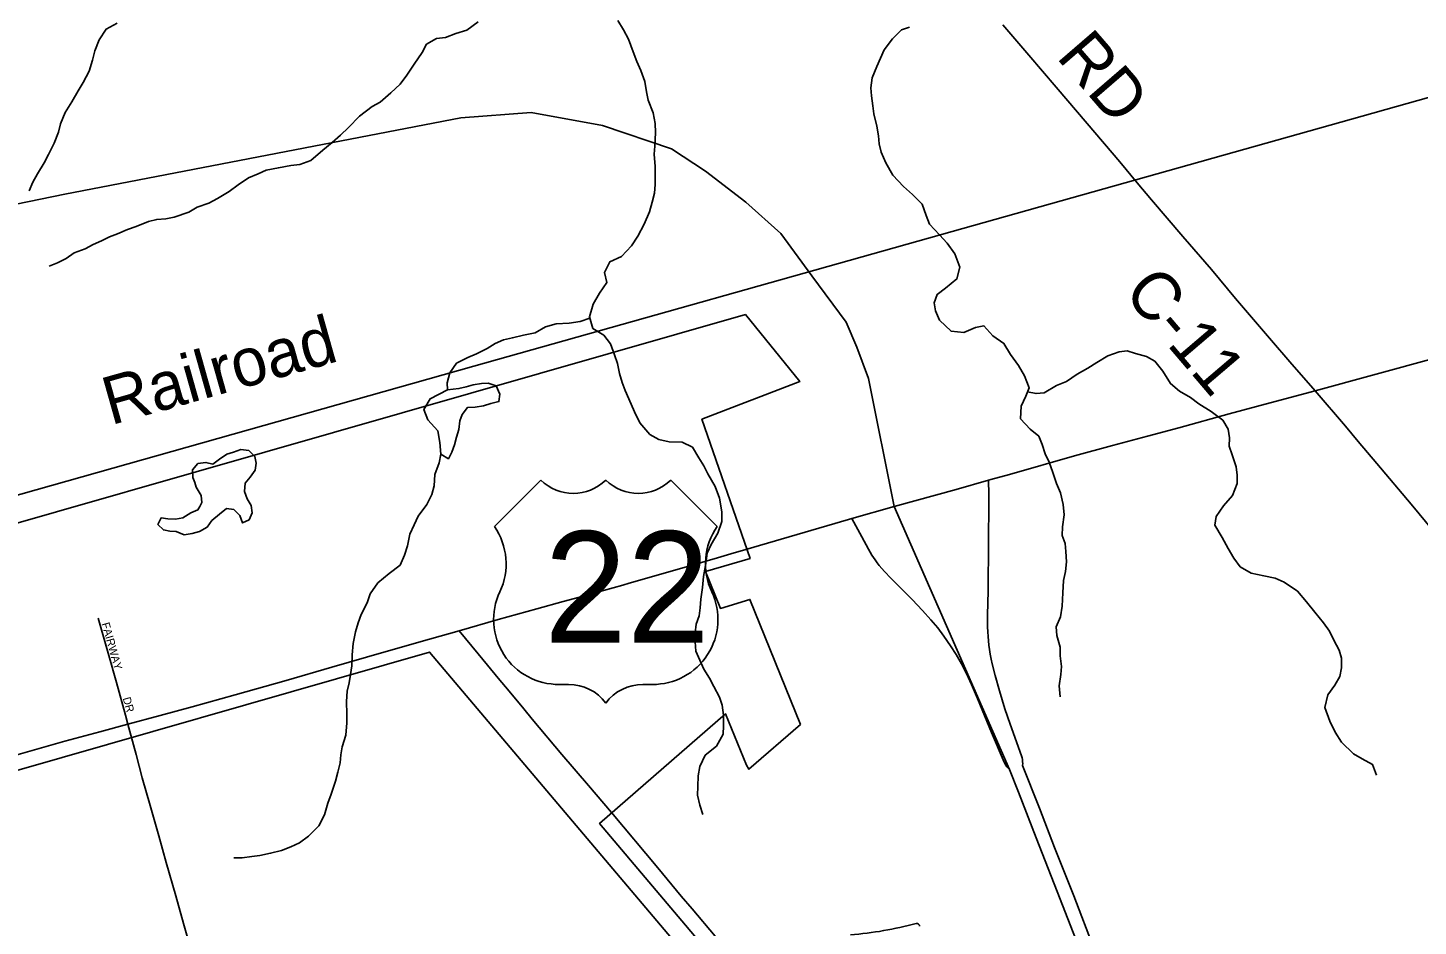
# Model space of a CAD drawing. Extents: x 1442749 to 1756758, y 235267 to 677782.
# Drawn here: x 1603104 to 1611789, y 530141 to 535753 of the extents above; entities that cross this region are included whole.
import ezdxf

# ---------------------------------------------------------------- set-up
doc = ezdxf.new("R2010")
doc.units = 0
for name, color, linetype in [('GM_P_State_Alignment', 7, 'Continuous'), ('GM_X_City_Street', 7, 'Continuous'), ('GM_X_City_Street_Text', 7, 'Continuous'), ('GM_X_Corporation', 7, 'Continuous'), ('GM_X_County_Road', 7, 'Continuous'), ('GM_X_County_Road_Text', 7, 'Continuous'), ('GM_X_Minor_Lake', 7, 'Continuous'), ('GM_X_Minor_River', 7, 'Continuous'), ('GM_X_Rail_Line', 7, 'Continuous'), ('GM_X_Rail_Line_Text', 7, 'Continuous'), ('GM_X_State_Route', 7, 'Continuous'), ('GM_X_State_Shield', 7, 'Continuous'), ('GM_X_US_Location', 7, 'Continuous'), ('GM_X_US_Route', 7, 'Continuous'), ('GM_X_US_Shield', 7, 'Continuous')]:
    doc.layers.add(name, color=color, linetype=linetype)

msp = doc.modelspace()

# ---------------------------------------------------------------- linework, layer by layer
at = {"layer": 'GM_P_State_Alignment'}
for points in [[(1602490.9, 534540.5), (1603334.8, 534713.2), (1605809.5, 535190.7), (1606248.1, 535223.2), (1606694.8, 535141.9), (1607125.2, 534995.7), (1607336.4, 534857.7), (1607588.2, 534662.8), (1607807.4, 534467.9), (1608002.5, 534203.6), (1608216, 533914.5), (1608283.2, 533757.6), (1608356.1, 533561.4), (1608516.5, 532762.3)], [(1608516.5, 532762.3), (1609236.7, 531120.1)]]:
    msp.add_lwpolyline(points, dxfattribs=at)
at = {"layer": 'GM_X_City_Street'}
for points in [[(1603728.9, 531403.4), (1603714, 531459.3), (1603656.9, 531664.2), (1603605.4, 531846.3), (1603543.5, 532064.9)], [(1604275.1, 529462.3), (1604235.3, 529602.6), (1604187.1, 529772.8), (1604133.1, 529961.9), (1604077.4, 530157.4), (1604028.1, 530330.8), (1603968.8, 530538.9), (1603921.7, 530706.1), (1603867.8, 530895.2), (1603819.1, 531068.8), (1603779.9, 531213.5), (1603741.1, 531356.6), (1603728.9, 531403.4)]]:
    msp.add_lwpolyline(points, dxfattribs=at)
at = {"layer": 'GM_X_Corporation'}
msp.add_lwpolyline([(1599850.2, 531747), (1607586.2, 533961), (1607925.7, 533543.2), (1607315, 533307.6), (1607615.7, 532438.7), (1607336.7, 532357), (1607430.1, 532125.8), (1607614.7, 532182.2), (1607930.3, 531401), (1607608.8, 531121.5), (1607592.4, 531146.6), (1607462.8, 531467.5), (1606675.9, 530783.4), (1609576.5, 527353.3), (1609668.7, 527239), (1609063.1, 526743.1), (1607767.9, 528274.8), (1607062.1, 527703.1), (1606189.4, 528248.5), (1606847.5, 528884.2), (1607206.9, 528613.3), (1607904.2, 529145.1), (1605613.8, 531853.4), (1602735.9, 531028)], dxfattribs=at)
at = {"layer": 'GM_X_County_Road'}
for points in [[(1611146.3, 533485.5), (1610988.1, 533665.5), (1610872.6, 533799.9), (1610648.7, 534061.7), (1610497.2, 534242.9), (1610319, 534448.8), (1610123.4, 534678.6), (1610034.7, 534784.1), (1609925, 534914.7), (1609721.3, 535155), (1609527.8, 535382.3), (1609356.5, 535581.3), (1609193.9, 535770.2)], [(1616061.8, 527721.7), (1615880.4, 527923.8), (1615777.9, 528043.3), (1615653.6, 528187.4), (1615413.7, 528469.9), (1615095.4, 528840.9), (1614595.4, 529430.5), (1614444.9, 529605.4), (1614212.9, 529877.4), (1614058.2, 530055.9), (1613941.2, 530193.2), (1613700.5, 530475.2), (1613366.2, 530866.9), (1613180.6, 531083.8), (1612938.5, 531368.8), (1612521.9, 531858.6), (1612333.3, 532081.4), (1612188.8, 532251.4), (1611885.9, 532609.5), (1611744.6, 532777.9), (1611530.6, 533030.9), (1611414.2, 533168.7), (1611334.2, 533264.3), (1611146.3, 533485.5)]]:
    msp.add_lwpolyline(points, dxfattribs=at)
at = {"layer": 'GM_X_Minor_Lake'}
for points in [[(1605725.1, 533491.2), (1605617.8, 533435.3), (1605576.9, 533367.6), (1605602.2, 533303.1), (1605665.5, 533234.2), (1605676.7, 533161.9), (1605683.9, 533089.6)], [(1605683.9, 533089.6), (1605731.6, 533060.9), (1605752.2, 533102.8), (1605768.7, 533146.8), (1605781.3, 533194.8), (1605795.9, 533242.7), (1605802.6, 533296.8), (1605817.1, 533336.8), (1605849.7, 533380.5), (1605897.8, 533382), (1605950, 533391.4), (1605996.3, 533404.9), (1606046.5, 533418.4), (1606053.1, 533464.4), (1606029.7, 533516.8), (1605979.7, 533533.5), (1605937.6, 533529.9), (1605885.4, 533522.5), (1605841.2, 533509), (1605797, 533499.4), (1605725.1, 533491.2)], [(1604456.5, 532856.9), (1604461.1, 532909), (1604493.7, 532946.7), (1604524.2, 532988.5), (1604530.8, 533032.6), (1604521.2, 533074.8), (1604483.6, 533113.3), (1604433.6, 533117.9), (1604389.3, 533102.4), (1604347, 533088.8), (1604300.6, 533057.3), (1604260.1, 533027.6), (1604216.1, 533038.2), (1604166, 533030.7), (1604133.4, 532991), (1604134.9, 532942.8), (1604146.5, 532912.6), (1604156.2, 532882.4), (1604185.7, 532831.9), (1604191.1, 532787.7), (1604177.7, 532762.7)], [(1604177.7, 532762.7), (1604166.5, 532741.9), (1604122.2, 532722.3), (1604071.8, 532692.8), (1604025.6, 532683.3), (1603977.5, 532685.9), (1603937.5, 532692.3), (1603916.9, 532650.5), (1603950.6, 532616), (1603990.6, 532609.5), (1604030.7, 532607), (1604080.5, 532586.4), (1604130.7, 532593.9), (1604177, 532607.4), (1604223.4, 532632.9), (1604253.9, 532674.7), (1604300.5, 532714.3), (1604345, 532749.9), (1604391, 532743.3), (1604428.7, 532706.8), (1604444.2, 532660.5), (1604486.5, 532680), (1604505, 532724), (1604499.6, 532768.2), (1604474, 532810.6), (1604456.5, 532856.9)]]:
    msp.add_lwpolyline(points, dxfattribs=at)
at = {"layer": 'GM_X_Minor_River'}
for points in [[(1603661.5, 535782.3), (1603592.9, 535745), (1603550, 535677.3), (1603523.1, 535609.4), (1603508.4, 535551.4), (1603487.5, 535481.5), (1603450.6, 535411.7), (1603418, 535359.9), (1603379, 535290.2), (1603338.2, 535224.4), (1603307.3, 535152.6), (1603294.6, 535100.6), (1603267.8, 535032.7), (1603232.8, 534960.9), (1603206.2, 534909.1), (1603165.3, 534841.3), (1603134.6, 534787.5), (1603111.9, 534733.6)], [(1605916.4, 535790.6), (1605845.6, 535737.3), (1605777.2, 535716), (1605712.8, 535692.7), (1605656.6, 535685.3), (1605594, 535649.9), (1605567.3, 535598), (1605516.4, 535526.4), (1605471.5, 535456.8), (1605430.7, 535401), (1605371.9, 535345.6), (1605305.1, 535288.2), (1605254.7, 535260.7), (1605175.8, 535201.4), (1605106.8, 535130), (1605056.1, 535082.4), (1605005.5, 535036.9), (1604946.8, 534987.4), (1604871.9, 534924.1), (1604803.4, 534898.8), (1604747.2, 534893.4), (1604668.9, 534878.3), (1604592.6, 534863.1), (1604542.2, 534839.6), (1604481.8, 534816.2), (1604417.1, 534770.8), (1604362.5, 534729.3), (1604287.8, 534686.1), (1604235.3, 534656.6), (1604160.9, 534631.4), (1604110.4, 534601.9), (1604017.9, 534568.8), (1603965.6, 534559.4), (1603909.5, 534556), (1603857.2, 534542.6), (1603780.7, 534511.4), (1603726.3, 534491.9), (1603663.9, 534466.6), (1603613.6, 534447.1), (1603563.1, 534421.6), (1603512.8, 534398.1), (1603462.4, 534372.6), (1603393.9, 534347.3), (1603343.4, 534311.8), (1603288.9, 534284.3), (1603236.6, 534262.9)], [(1606790.3, 535798.6), (1606825.7, 535740.1), (1606857, 535681.5), (1606886.2, 535603), (1606907.5, 535542.6), (1606932.9, 535486.1), (1606958.1, 535417.7), (1606969.4, 535353.3), (1606978.8, 535301.1), (1607009.9, 535220.5), (1607023.2, 535154.2), (1607024.5, 535098), (1607021.5, 535013.8), (1607016.9, 534963.7), (1607022, 534885.4), (1607023.3, 534827.2), (1607022.6, 534773.1), (1607018, 534719), (1607003.3, 534663), (1606986.5, 534603), (1606953.5, 534525.2), (1606914.6, 534451.4), (1606875.8, 534391.7), (1606812.9, 534324.2), (1606740.3, 534290.9), (1606705.5, 534225.2), (1606720.7, 534160.8), (1606675.9, 534095.1), (1606635, 534025.4), (1606612, 533947.4), (1606633.2, 533875), (1606702.8, 533832.1), (1606744.3, 533779.4), (1606769.5, 533710.9), (1606786.9, 533656.6), (1606800.2, 533594.3), (1606817.6, 533537.9), (1606835, 533487.6), (1606858.4, 533435.1), (1606893.6, 533354.5), (1606926.8, 533285.9), (1606990.1, 533213), (1607045.8, 533180.3), (1607109.8, 533167.5), (1607191.9, 533164.6), (1607255.7, 533133.8), (1607295, 533067.1), (1607326.5, 533016.6), (1607351.9, 532966.2), (1607397.1, 532887.4), (1607424.3, 532814.9), (1607439.3, 532728.5), (1607438.6, 532668.3), (1607413.7, 532596.4), (1607372.8, 532524.7), (1607348.1, 532470.8), (1607337.1, 532394.7), (1607324.3, 532324.6), (1607317.5, 532256.5), (1607308.6, 532184.4), (1607303.9, 532130.3), (1607297.3, 532080.2), (1607278.7, 532028.3), (1607272, 531974.2), (1607273.4, 531918), (1607276.7, 531859.8), (1607302.1, 531803.4), (1607327.5, 531746.9), (1607362.9, 531690.3), (1607388.3, 531637.9), (1607425.6, 531571.3), (1607441, 531520.9), (1607450.3, 531458.7), (1607449.5, 531392.5), (1607446.9, 531340.4), (1607406, 531266.6), (1607335.1, 531209.2), (1607302.2, 531139.4), (1607291.5, 531079.4), (1607288.7, 531013.2), (1607288.1, 530959), (1607301.4, 530896.7), (1607320.7, 530838.3)], [(1608611.7, 535755.7), (1608561.4, 535740.2), (1608504.6, 535682.7), (1608453.7, 535615.1), (1608408.3, 535511.3), (1608379.4, 535439.5), (1608370.7, 535377.4), (1608374.1, 535327.2), (1608383.3, 535264.9), (1608388.8, 535214.7), (1608407.9, 535138.3), (1608417.2, 535078), (1608422.6, 535027.8), (1608434, 534975.5), (1608463.3, 534909), (1608508.5, 534832.3), (1608573.8, 534761.3), (1608631.3, 534710.5), (1608690.7, 534651.7), (1608716, 534581.2), (1608737.4, 534526.8), (1608798.7, 534459.9), (1608846.2, 534407.2), (1608895.5, 534340.5), (1608926.6, 534257.9), (1608907.7, 534183.9), (1608836.8, 534126.5), (1608784.2, 534087), (1608765.6, 534035.1), (1608773, 533984.8), (1608798.4, 533926.4), (1608871.7, 533857.4), (1608951.8, 533848.4), (1609024.3, 533879.7), (1609076.5, 533891.1), (1609131.9, 533828.3), (1609201.5, 533781.4), (1609242.8, 533712.7), (1609292.1, 533643.9), (1609329.4, 533579.3), (1609358.6, 533504.8), (1609337.9, 533450.9), (1609309.1, 533389), (1609304.2, 533310.9), (1609365.5, 533246), (1609419.1, 533201.2), (1609440.5, 533150.8), (1609459.9, 533092.4), (1609483.3, 533040), (1609506.6, 532975.6), (1609529.9, 532907.1), (1609555.2, 532848.7), (1609572.4, 532774.2), (1609577.6, 532710), (1609566.7, 532635.9), (1609566.1, 532581.8), (1609583.5, 532531.4), (1609588.9, 532481.2), (1609592.2, 532417), (1609585.5, 532356.9), (1609572.8, 532300.9), (1609569.8, 532222.7), (1609564.9, 532140.5), (1609554.1, 532074.4), (1609527.2, 532010.6), (1609532.6, 531956.3), (1609551.8, 531883.9), (1609553.2, 531829.7), (1609560.4, 531763.5), (1609557.8, 531713.3), (1609546.9, 531643.3), (1609552.1, 531573)], [(1606614.7, 533938.2), (1606553.5, 533918), (1606485.2, 533906.8), (1606405, 533903.7), (1606338.7, 533884.4), (1606274.1, 533847), (1606199.7, 533831.8), (1606131.4, 533816.5), (1606075.1, 533803.1), (1606022.8, 533781.7), (1605972.3, 533750.2), (1605905.8, 533716.8), (1605853.4, 533693.4), (1605782.8, 533658.1), (1605740, 533598.4), (1605723.2, 533534.4), (1605725.1, 533491.2), (1605617.8, 533435.3), (1605576.9, 533367.6), (1605602.2, 533303.1), (1605665.5, 533234.2), (1605676.7, 533161.9), (1605683.9, 533089.6), (1605673.2, 533035.5), (1605646.3, 532961.6), (1605641.4, 532891.5), (1605626.8, 532837.5), (1605596, 532775.7), (1605543, 532702.1), (1605516.3, 532648.2), (1605489.5, 532590.3), (1605476.6, 532516.3), (1605457.9, 532458.3), (1605429.1, 532396.5), (1605360.4, 532343.1), (1605289.5, 532285.7), (1605242.6, 532216.1), (1605223.9, 532160.1), (1605187, 532088.3), (1605168.3, 532036.4), (1605151.6, 531980.4), (1605136.7, 531906.4), (1605129.9, 531836.2), (1605127.1, 531768.1), (1605120.4, 531714), (1605111.8, 531661.9), (1605099.1, 531609.9), (1605094.3, 531543.8), (1605097.4, 531465.5), (1605096.8, 531411.4), (1605089.9, 531335.2), (1605067, 531261.3), (1605058.4, 531211.2), (1605055.8, 531161.1), (1605041, 531103.1), (1605026.4, 531047.1), (1604999.3, 530965.2), (1604978.6, 530909.3), (1604957.7, 530837.3), (1604920.8, 530767.5), (1604857.9, 530704), (1604801.3, 530662.5), (1604746.9, 530637.1), (1604688.5, 530613.7), (1604620.2, 530596.4), (1604553.9, 530583.1), (1604503.7, 530575.7), (1604443.5, 530568.3), (1604391.4, 530568.9)], [(1609348.9, 533479.6), (1609402.2, 533468.2), (1609452.4, 533473.6), (1609529.1, 533518.9), (1609591.5, 533544.2), (1609658.2, 533589.6), (1609724.8, 533627), (1609781.3, 533662.4), (1609850, 533703.8), (1609920.4, 533729), (1609970.6, 533734.5), (1610022.5, 533717.8), (1610092.4, 533699), (1610144.2, 533670.3), (1610193.6, 533607.5), (1610242.7, 533530.8), (1610298.3, 533482), (1610366, 533443.1), (1610419.6, 533404.4), (1610495.2, 533355.4), (1610568.7, 533302.4), (1610602.1, 533245.8), (1610611.5, 533191.6), (1610608.9, 533139.5), (1610626.3, 533085.1), (1610651.5, 533010.6), (1610658.9, 532958.4), (1610658.2, 532906.2), (1610629.3, 532830.3), (1610572.4, 532766.8), (1610527.5, 532701.1), (1610518.9, 532645.1), (1610564, 532568.3), (1610601.3, 532499.7), (1610636.7, 532439.1), (1610678.1, 532386.5), (1610745.8, 532345.6), (1610825.8, 532328.7), (1610895.8, 532315.8), (1610951.6, 532289.1), (1611035.1, 532234), (1611092.4, 532167.1), (1611143.8, 532102.4), (1611197.1, 532035.6), (1611234.5, 531983), (1611262, 531928.5), (1611295.3, 531865.9), (1611310.7, 531815.6), (1611310, 531755.5), (1611299.4, 531701.4), (1611268.6, 531645.6), (1611225.8, 531585.9), (1611206.9, 531507.9), (1611237.9, 531421.3), (1611271.2, 531352.7), (1611310.5, 531290.1), (1611385.8, 531217), (1611439.6, 531186.3), (1611503.3, 531151.5), (1611528.6, 531085)]]:
    msp.add_lwpolyline(points, dxfattribs=at)
at = {"layer": 'GM_X_Rail_Line'}
msp.add_lwpolyline([(1602593, 532708.2), (1605889.2, 533638.1), (1608878.6, 534479.8), (1615229.4, 536269.1), (1618947.6, 537317.7), (1620089.8, 537639.4), (1622992.7, 538441.5), (1624973.8, 539013.5)], dxfattribs=at)
at = {"layer": 'GM_X_State_Route'}
for points in [[(1609105.6, 532927.3), (1609106.6, 532838.3), (1609107.1, 532783.6), (1609104.3, 532541.1), (1609102, 532233), (1609099.4, 532085.5), (1609099.3, 532010.1), (1609100.5, 531979.9), (1609102, 531951.1), (1609104.4, 531923.7), (1609107.7, 531895.7), (1609111.5, 531869.4), (1609116.3, 531840.7), (1609122.2, 531809.8), (1609128.9, 531779.6), (1609147, 531706.4), (1609173.4, 531611.7), (1609207.8, 531498.8), (1609240.2, 531403.8), (1609310.9, 531206.1), (1609314.8, 531193.4), (1609317, 531181.4), (1609318.3, 531168.3), (1609319, 531157.6), (1609318.1, 531145), (1609423.6, 530878.6), (1609517.8, 530633.6), (1609637.2, 530331.5), (1609766.1, 529997.9)], [(1608251, 532688.3), (1608314.3, 532573.5), (1608355.9, 532495.6), (1608376.9, 532458.6), (1608396.7, 532428.5), (1608409.5, 532411.2), (1608422.6, 532394.6), (1608454.8, 532357.5), (1608495.7, 532314.9), (1608627.5, 532182.6), (1608693.2, 532113.8), (1608745.7, 532055.3), (1608787.6, 532004.8), (1608827, 531952.4), (1608867.9, 531893), (1608902.9, 531837.6), (1608935.5, 531780.7), (1608967.3, 531719.6), (1608999.2, 531651.3), (1609035.6, 531562.8), (1609124.2, 531351.1), (1609196.6, 531181), (1609207.8, 531158.2), (1609213.4, 531147.5), (1609220.4, 531137.1), (1609227.5, 531128.4), (1609236.7, 531120.1)], [(1605798, 531986), (1605916.8, 531842), (1606053.1, 531678.9), (1606101, 531620.9)], [(1606101, 531620.9), (1606201.6, 531499)], [(1606201.6, 531499), (1606254.8, 531434.6), (1606438.9, 531213.1), (1606606.6, 531020), (1606749.3, 530850.7)], [(1609236.7, 531120.1), (1609291.7, 530978.1), (1609401.9, 530693.5), (1609533.9, 530357.5), (1609818.9, 529626.7), (1609915.2, 529382.4), (1610040.6, 529061.4), (1610089.8, 528929), (1610128.8, 528817.3), (1610153.9, 528739.1), (1610180.2, 528647.5), (1610211.3, 528530), (1610239.3, 528415), (1610258, 528324.9), (1610267.1, 528275.1), (1610276.5, 528221.4), (1610290.2, 528133.7), (1610300.6, 528052.2), (1610310.7, 527954.2), (1610325.6, 527780.8), (1610331.5, 527700.6)], [(1606749.3, 530850.7), (1607038.6, 530505.9), (1607185.7, 530329.4), (1607252.9, 530248.7), (1607396.9, 530078.3), (1607485.3, 529972.6), (1607684.4, 529737), (1608040.6, 529308), (1608138.9, 529192.7), (1608265.8, 529043.6), (1608364.3, 528926.4), (1608680.7, 528550.5), (1608776.4, 528436.8), (1609018.1, 528147), (1609085.4, 528067.3), (1609143.7, 527999.6), (1609281.8, 527832.8), (1609404.3, 527687.1), (1609595.4, 527457.6), (1609730.5, 527290.9)]]:
    msp.add_lwpolyline(points, dxfattribs=at)
at = {"layer": 'GM_X_State_Shield'}
for centre, major_axis, start_param, end_param in [((1608054.3, 531555.5), (1845.5, 0), 4.814394, 5.042369), ((1608654.9, 530143.4), (19.4, 0), 6.141152, 7.989035)]:
    msp.add_ellipse(centre, major_axis=major_axis, ratio=0.8, start_param=start_param, end_param=end_param, dxfattribs=at)
at = {"layer": 'GM_X_US_Route'}
for points in [[(1611114.3, 533477), (1611146.3, 533485.5), (1611884.1, 533686), (1612184.8, 533768.1), (1612773.7, 533928), (1612922.6, 533968.1), (1613097, 534014.1), (1613213, 534045.8), (1613334.4, 534079), (1613521.5, 534128.3), (1613977.5, 534251.7), (1614297.1, 534339.2), (1614683.6, 534443), (1615227.3, 534594.2), (1615651.8, 534708.6), (1615838.5, 534759.6), (1616075, 534827.4), (1616654.2, 534997.3), (1617126.4, 535135.7), (1617371.7, 535208.7), (1617599.3, 535275.1)], [(1608251, 532688.3), (1608516.5, 532762.3), (1608902.7, 532869.6), (1609105.6, 532927.3), (1609120.1, 532931.3), (1609236.3, 532963.4), (1609642.3, 533079.1), (1609880.5, 533143.3), (1610098, 533201), (1610294.7, 533254.1), (1610607.7, 533340.6), (1610778.6, 533387.2), (1611114.3, 533477)], [(1607674, 532518.8), (1607909.8, 532588.1), (1608230.8, 532682.4)], [(1608230.8, 532682.4), (1608251, 532688.3)], [(1607567.7, 532487.6), (1607674, 532518.8)], [(1606859.4, 532283.2), (1607072.8, 532343.2), (1607268.7, 532399.5), (1607412, 532441.4), (1607517.1, 532472.7), (1607567.7, 532487.6)], [(1606448, 532168.2), (1606519.8, 532187.6), (1606820.4, 532272.2), (1606859.4, 532283.2)], [(1605798, 531986), (1606042, 532056.3), (1606282.8, 532123.4), (1606448, 532168.2)], [(1603366, 531304.5), (1603552.7, 531355.8), (1603728.9, 531403.4), (1603931.6, 531458.1), (1604131.2, 531511), (1604398.2, 531585.7), (1604716.9, 531676), (1605003.7, 531758.7), (1605328.4, 531852.1), (1605612.7, 531933.9), (1605798, 531986)], [(1599333.3, 530149.7), (1599393.1, 530166.5), (1599694.5, 530253.4), (1599900.6, 530311.5), (1600124.2, 530374.6), (1600399.9, 530455.2), (1600769, 530566), (1601060.8, 530650.9), (1601380.7, 530741.9), (1601496.5, 530774.8), (1601830.3, 530869.3), (1601993.5, 530915.8), (1602300.5, 531002.6), (1602331.7, 531011.4), (1602698.4, 531115.1), (1602851.5, 531158.7), (1603028.6, 531209.2), (1603335.4, 531296.1), (1603366, 531304.5)]]:
    msp.add_lwpolyline(points, dxfattribs=at)
at = {"layer": 'GM_X_US_Shield'}
for p, q in [((1606308.3, 532927.4), (1606018.2, 532637.4)), ((1607410.4, 532637.4), (1607120.4, 532927.4)), ((1606424.3, 531651.3), (1606482.3, 531651.3)), ((1606946.4, 531651.3), (1607004.4, 531651.3))]:
    msp.add_line(p, q, dxfattribs=at)
for centre, radius, start, end in [((1606511.3, 533134.6), 290, 225.573, 314.427), ((1606917.3, 533134.6), 290, 225.573, 314.427), ((1605685.6, 532404.5), 406.1, 334.54712, 35.00093), ((1607743, 532404.5), 406.1, 144.99907, 205.45288), ((1606419.8, 532057.3), 406.1, 154.83192, 270.63826), ((1607008.9, 532057.3), 406.1, 269.36174, 25.16808), ((1606482.3, 531361.2), 290, 36.8699, 90), ((1606946.4, 531361.2), 290, 90, 143.1301)]:
    msp.add_arc(centre, radius, start, end, dxfattribs=at)

# ---------------------------------------------------------------- texts
at = {"layer": 'GM_X_City_Street_Text'}
for s, rotation, p in [('FAIRWAY', 285.70726, (1603564.3, 532031)), ('DR', 285.52913, (1603696.2, 531564.8))]:
    msp.add_text(s, height=50, rotation=rotation, dxfattribs=at).set_placement(p)
at = {"layer": 'GM_X_County_Road_Text'}
for s, rotation, p in [('RD', 310.81354, (1609522.9, 535568.7)), ('C-11', 310.41655, (1609940.7, 534096))]:
    msp.add_text(s, height=300, rotation=rotation, dxfattribs=at).set_placement(p)
at = {"layer": 'GM_X_Rail_Line_Text'}
msp.add_text('Railroad', height=299, rotation=15.74069, dxfattribs=at).set_placement((1603622.1, 533269.3))
at = {"layer": 'GM_X_US_Location'}
for s in ['0', '/']:
    msp.add_text(s, height=1, dxfattribs=at).set_placement((1606714, 532254.9))
msp.add_text('22', height=1, rotation=0.00001, dxfattribs=at).set_placement((1606507.5, 532047.9))
at = {"layer": 'GM_X_US_Shield'}
msp.add_text('22', height=696.1, dxfattribs=at).set_placement((1606329, 531912.3))

doc.saveas('drawing.dxf')
